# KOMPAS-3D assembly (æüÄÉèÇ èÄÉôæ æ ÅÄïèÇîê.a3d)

Referenced files in D:\МОДЕЛЬ ТАНКА Т90\СБОРКИ\СБОРКА КОРПУСА ШТАМПОВКА\: СБОРКА КОРПУС.a3d, Сборка полка надгусеничная левая.a3d, Сборка полка надгусеничная правая.a3d
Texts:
  СБОРКА КОРУС С ПОЛКАМИ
